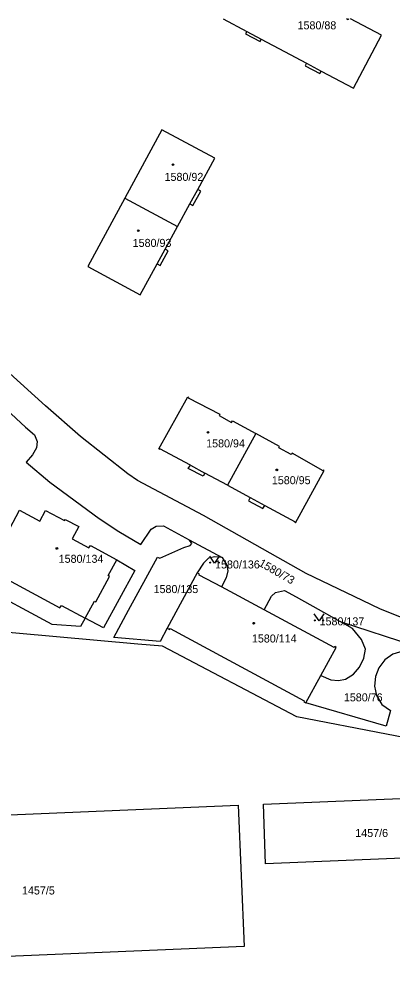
# Model space of a CAD drawing. Extents: x -736397 to -735924, y -1118983 to -1118245.
# Drawn here: x -736149.3 to -736070.2, y -1118445.4 to -1118244.9 of the extents above; entities that cross this region are included whole.
import ezdxf

# ---------------------------------------------------------------- set-up
doc = ezdxf.new("R2010")
doc.units = 0
for name, color, linetype in [('Vrstva 1', 7, 'Continuous'), ('Vrstva 18', 7, 'Continuous'), ('Vrstva 19', 7, 'Continuous'), ('Vrstva 25', 7, 'Continuous'), ('Vrstva 4', 7, 'Continuous')]:
    doc.layers.add(name, color=color, linetype=linetype)

msp = doc.modelspace()

# ---------------------------------------------------------------- linework, layer by layer
at = {"layer": 'Vrstva 1'}
for p, q in [((-736126.82, -1118282.98), (-736115.67, -1118288.99)), ((-736115.67, -1118288.99), (-736113.05, -1118284.19)), ((-736118.29, -1118293.79), (-736115.67, -1118288.99)), ((-736099.05, -1118332.96), (-736105.07, -1118343.93)), ((-736105.07, -1118343.93), (-736109.85, -1118341.34)), ((-736105.07, -1118343.93), (-736100.26, -1118346.53)), ((-736113.2, -1118355.5), (-736106.2, -1118359.23)), ((-736111.5, -1118362.52), (-736117.84, -1118374.26)), ((-736097.3, -1118370.36), (-736106.34, -1118365.52)), ((-736081.16, -1118372.84), (-736059.31, -1118379.99)), ((-736088.43, -1118390.14), (-736085.25, -1118384.34))]:
    msp.add_line(p, q, dxfattribs=at)
for points in [[(-736105.96, -1118244.9), (-736100.97, -1118247.56)], [(-736085.17, -1118255.98), (-736078.32, -1118259.64), (-736072.39, -1118248.36), (-736078.97, -1118244.9)], [(-736079.42, -1118244.9), (-736079.51, -1118245.07), (-736079.84, -1118244.9)], [(-736100.97, -1118247.56), (-736101.24, -1118248.07), (-736098.17, -1118249.71), (-736097.89, -1118249.2)], [(-736097.89, -1118249.2), (-736092.96, -1118251.83), (-736088.29, -1118254.32)], [(-736088.29, -1118254.32), (-736088.57, -1118254.83), (-736085.45, -1118256.5), (-736085.17, -1118255.98)], [(-736111.37, -1118281.11), (-736107.74, -1118274.47), (-736118.96, -1118268.47), (-736126.82, -1118282.98)], [(-736113.05, -1118284.19), (-736112.4, -1118284.54), (-736110.73, -1118281.46), (-736111.37, -1118281.11)], [(-736126.82, -1118282.98), (-736134.68, -1118297.49), (-736123.6, -1118303.51), (-736119.98, -1118296.89)], [(-736119.98, -1118296.89), (-736119.34, -1118297.24), (-736117.65, -1118294.14), (-736118.29, -1118293.79)], [(-735981.63, -1118406.73), (-736007.57, -1118392.76), (-736021.29, -1118385.4), (-736028.1, -1118381.59), (-736032.04, -1118379.73), (-736035.9, -1118378.2), (-736040.7, -1118376.65), (-736044.01, -1118375.88), (-736047.06, -1118375.3), (-736050.57, -1118374.86), (-736059.63, -1118373.8), (-736063.58, -1118373.19), (-736068.55, -1118371.85), (-736072.64, -1118370.2), (-736076.44, -1118368.41), (-736088.36, -1118362.67), (-736110.12, -1118350.32), (-736124.12, -1118342.88), (-736126.16, -1118341.48), (-736136.25, -1118333.56), (-736143.63, -1118327.06), (-736151.23, -1118320.2)], [(-736112.94, -1118339.68), (-736119.39, -1118336.19), (-736119.44, -1118336.3), (-736119.62, -1118336.2), (-736113.5, -1118325.14), (-736113.34, -1118325.22), (-736113.41, -1118325.36), (-736106.67, -1118328.83), (-736106.83, -1118329.14), (-736104.2, -1118330.57), (-736104.03, -1118330.26), (-736099.05, -1118332.96)], [(-736151.91, -1118327.84), (-736147.88, -1118331.57), (-736145.97, -1118333.22), (-736145.45, -1118334.65), (-736145.53, -1118336), (-736146.42, -1118337.49), (-736147.72, -1118339), (-736142.73, -1118343.24), (-736132.28, -1118350.99), (-736128.12, -1118353.73), (-736123.41, -1118356.52), (-736121.25, -1118353.28), (-736120.22, -1118352.62), (-736118.6, -1118352.53), (-736113.2, -1118355.5)], [(-736097.18, -1118348.19), (-736090.73, -1118351.68), (-736090.79, -1118351.78), (-736090.61, -1118351.88), (-736084.55, -1118340.79), (-736084.72, -1118340.69), (-736084.8, -1118340.83), (-736091.36, -1118337.1), (-736091.53, -1118337.41), (-736094.21, -1118335.96), (-736094.05, -1118335.66), (-736099.05, -1118332.96)], [(-736109.85, -1118341.34), (-736110.21, -1118342), (-736113.38, -1118340.34), (-736112.94, -1118339.68)], [(-736100.26, -1118346.53), (-736100.63, -1118347.21), (-736097.55, -1118348.88), (-736097.18, -1118348.19)], [(-736153.37, -1118357.01), (-736149.18, -1118349.24), (-736144.88, -1118351.55), (-736143.64, -1118349.26), (-736139.62, -1118351.44), (-736139.47, -1118351.16), (-736136.61, -1118352.7), (-736137.97, -1118355.27), (-736134.43, -1118357.19), (-736134.13, -1118356.71), (-736128.51, -1118359.75)], [(-736117.84, -1118374.26), (-736119.36, -1118377.08), (-736129.18, -1118376.27), (-736126.02, -1118370.43), (-736119.87, -1118359.2), (-736119.42, -1118359.4), (-736114.3, -1118357.13), (-736112.96, -1118356.7), (-736112.66, -1118356.27), (-736112.91, -1118355.84), (-736113.2, -1118355.5)], [(-736106.2, -1118359.23), (-736107.74, -1118359.11), (-736109.08, -1118359.37), (-736110.16, -1118360.45), (-736111.5, -1118362.52)], [(-736106.2, -1118359.23), (-736105.2, -1118360.89), (-736105.02, -1118362.06), (-736105.32, -1118363.55), (-736106.34, -1118365.52)], [(-736128.51, -1118359.75), (-736124.74, -1118361.99), (-736131.36, -1118374.21), (-736135.22, -1118372.18)], [(-736106.34, -1118365.52), (-736111.07, -1118362.98), (-736110.97, -1118362.8), (-736111.5, -1118362.52)], [(-736135.22, -1118372.18), (-736136.24, -1118373.94), (-736142.22, -1118373.5), (-736157.52, -1118365.27)], [(-736097.3, -1118370.36), (-736095.7, -1118367.46), (-736094.89, -1118366.69), (-736093, -1118366.28), (-736090.47, -1118367.63), (-736081.16, -1118372.84)], [(-736052.29, -1118402.89), (-736052.32, -1118400.48), (-736090.36, -1118393.09), (-736118.86, -1118378.12), (-736124.09, -1118377.65), (-736210.35, -1118369.86)], [(-736085.25, -1118384.34), (-736081.99, -1118378.4), (-736082.32, -1118378.16), (-736082.42, -1118378.34), (-736097.3, -1118370.36)], [(-736085.25, -1118384.34), (-736083.12, -1118385.26), (-736081.56, -1118385.38), (-736080.07, -1118385.07), (-736078.33, -1118384.05), (-736077.1, -1118382.53), (-736076.18, -1118380.62), (-736075.77, -1118378.73), (-736076.63, -1118376.68), (-736078.53, -1118374.33), (-736081.16, -1118372.84)], [(-736117.84, -1118374.26), (-736117.36, -1118374.52), (-736117.25, -1118374.31), (-736088.8, -1118389.69), (-736088.91, -1118389.89), (-736088.43, -1118390.14)], [(-736059.31, -1118379.99), (-736065.33, -1118379.12), (-736067.91, -1118379.12), (-736070.03, -1118379.76), (-736071.67, -1118380.97), (-736072.98, -1118382.66), (-736073.71, -1118384.56), (-736073.92, -1118386.61), (-736073.5, -1118388.55), (-736072.34, -1118390.47), (-736070.47, -1118391.75), (-736071.45, -1118395.11), (-736088.43, -1118390.14)], [(-736054.44, -1118417.58), (-736054.24, -1118422.54), (-736096.98, -1118424.31), (-736097.43, -1118411.63), (-736054.76, -1118409.87), (-736054.56, -1118414.79)], [(-736191.24, -1118443.78), (-736195.37, -1118444.04), (-736196.5, -1118417.85), (-736186.33, -1118417.24), (-736186.41, -1118415.38), (-736102.77, -1118411.87), (-736101.51, -1118441.88), (-736185.15, -1118445.39), (-736185.18, -1118444.69)]]:
    msp.add_lwpolyline(points, dxfattribs=at)
at = {"layer": 'Vrstva 25'}
for points in [[(-736106.83, -1118358.96), (-736107.83, -1118360.46), (-736108.83, -1118358.96)], [(-736084.66, -1118371.21), (-736085.66, -1118372.71), (-736086.66, -1118371.21)]]:
    msp.add_lwpolyline(points, dxfattribs=at)
for centre in [(-736108.73, -1118360.36), (-736106.93, -1118360.36), (-736086.56, -1118372.61), (-736084.76, -1118372.61)]:
    msp.add_circle(centre, 0.1, dxfattribs=at)
for centre, major_axis in [((-736116.61, -1118275.85), (0.18, 0)), ((-736123.98, -1118289.87), (0.18, 0)), ((-736109.21, -1118332.7), (0.18, 0)), ((-736094.61, -1118340.65), (0.18, 0)), ((-736141.24, -1118357.34), (0.18, 0)), ((-736099.5, -1118373.23), (-0.179, 0.02))]:
    msp.add_ellipse(centre, major_axis=major_axis, ratio=0.984808, dxfattribs=at)
at = {"layer": 'Vrstva 4'}
for p, q in [((-736100.97, -1118247.56), (-736097.89, -1118249.2)), ((-736088.29, -1118254.32), (-736085.17, -1118255.98)), ((-736113.05, -1118284.19), (-736111.37, -1118281.11)), ((-736119.98, -1118296.89), (-736118.29, -1118293.79)), ((-736112.94, -1118339.68), (-736109.85, -1118341.34)), ((-736100.26, -1118346.53), (-736097.18, -1118348.19))]:
    msp.add_line(p, q, dxfattribs=at)
for points in [[(-736155.13, -1118360.86), (-736151.16, -1118363), (-736151.69, -1118363.96), (-736140.59, -1118369.97), (-736140.27, -1118369.43), (-736135.22, -1118372.18)], [(-736135.22, -1118372.18), (-736133.24, -1118368.55), (-736132.98, -1118368.67), (-736130.08, -1118363.27), (-736130.35, -1118363.11), (-736128.51, -1118359.75)]]:
    msp.add_lwpolyline(points, dxfattribs=at)

# ---------------------------------------------------------------- texts
at = {"layer": 'Vrstva 18'}
for s, p in [('1580/136', (-736107.7, -1118361.59)), ('1580/135', (-736120.74, -1118366.82)), ('1580/137', (-736085.54, -1118373.67)), ('1580/76', (-736080.39, -1118389.81)), ('1457/6', (-736077.97, -1118418.61)), ('1457/5', (-736148.64, -1118430.82))]:
    msp.add_text(s, height=1.7, dxfattribs=at).set_placement(p)
msp.add_text('1580/73', height=1.7, rotation=330.2008, dxfattribs=at).set_placement((-736098.58, -1118360.93))
at = {"layer": 'Vrstva 19'}
for s, p in [('1580/88', (-736090.21, -1118247.11)), ('1580/92', (-736118.41, -1118279.29)), ('1580/93', (-736125.17, -1118293.31)), ('1580/94', (-736109.59, -1118335.88)), ('1580/95', (-736095.66, -1118343.7)), ('1580/134', (-736140.86, -1118360.39)), ('1580/114', (-736099.89, -1118377.31))]:
    msp.add_text(s, height=1.7, dxfattribs=at).set_placement(p)

doc.saveas('drawing.dxf')
